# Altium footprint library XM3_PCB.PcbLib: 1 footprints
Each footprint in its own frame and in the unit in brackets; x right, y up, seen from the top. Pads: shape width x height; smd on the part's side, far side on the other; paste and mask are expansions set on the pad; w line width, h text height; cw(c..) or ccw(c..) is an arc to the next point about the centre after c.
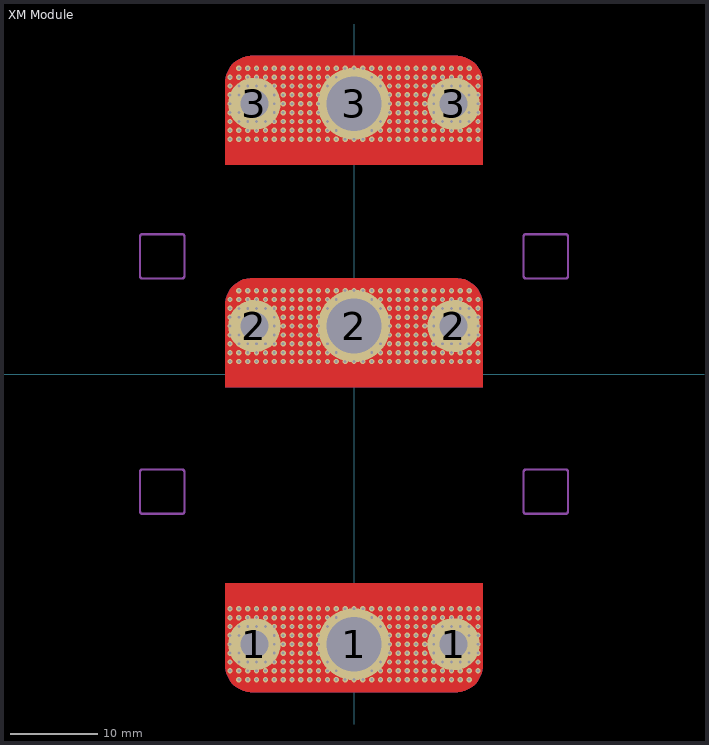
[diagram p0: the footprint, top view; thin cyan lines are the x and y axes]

## XM Module [mm]
pads (9):
  round 6 hole 3.2: 1(-11.43,-31) 1(11.43,-31) 2(-11.43,5.5) 2(11.43,5.5) 3(-11.43,31) 3(11.43,31)
  round 8.3 hole 6.3: 1(0,-31) 2(0,5.5) 3(0,31)
via 0,26.936 diameter 0.61 hole 0.33
via 1.016,26.936 diameter 0.61 hole 0.33
via 1.016,35.064 diameter 0.61 hole 0.33
via 2.032,26.936 diameter 0.61 hole 0.33
via 2.032,27.952 diameter 0.61 hole 0.33
via 2.032,34.048 diameter 0.61 hole 0.33
via 2.032,35.064 diameter 0.61 hole 0.33
via 3.048,26.936 diameter 0.61 hole 0.33
via 3.048,27.952 diameter 0.61 hole 0.33
via 3.048,28.968 diameter 0.61 hole 0.33
via 3.048,33.032 diameter 0.61 hole 0.33
via 3.048,34.048 diameter 0.61 hole 0.33
via 3.048,35.064 diameter 0.61 hole 0.33
via 4.064,26.936 diameter 0.61 hole 0.33
via 4.064,27.952 diameter 0.61 hole 0.33
via 4.064,28.968 diameter 0.61 hole 0.33
via 4.064,29.984 diameter 0.61 hole 0.33
via 4.064,31 diameter 0.61 hole 0.33
via 4.064,32.016 diameter 0.61 hole 0.33
via 4.064,33.032 diameter 0.61 hole 0.33
via 4.064,34.048 diameter 0.61 hole 0.33
via 4.064,35.064 diameter 0.61 hole 0.33
via 5.08,26.936 diameter 0.61 hole 0.33
via 5.08,27.952 diameter 0.61 hole 0.33
via 5.08,28.968 diameter 0.61 hole 0.33
via 5.08,29.984 diameter 0.61 hole 0.33
via 5.08,31 diameter 0.61 hole 0.33
via 5.08,32.016 diameter 0.61 hole 0.33
via 5.08,33.032 diameter 0.61 hole 0.33
via 5.08,34.048 diameter 0.61 hole 0.33
via 5.08,35.064 diameter 0.61 hole 0.33
via 6.096,26.936 diameter 0.61 hole 0.33
via 6.096,27.952 diameter 0.61 hole 0.33
via 6.096,28.968 diameter 0.61 hole 0.33
via 6.096,29.984 diameter 0.61 hole 0.33
via 6.096,31 diameter 0.61 hole 0.33
via 6.096,32.016 diameter 0.61 hole 0.33
via 6.096,33.032 diameter 0.61 hole 0.33
via 6.096,34.048 diameter 0.61 hole 0.33
via 6.096,35.064 diameter 0.61 hole 0.33
via 7.112,26.936 diameter 0.61 hole 0.33
via 7.112,27.952 diameter 0.61 hole 0.33
via 7.112,28.968 diameter 0.61 hole 0.33
via 7.112,29.984 diameter 0.61 hole 0.33
via 7.112,31 diameter 0.61 hole 0.33
via 7.112,32.016 diameter 0.61 hole 0.33
via 7.112,33.032 diameter 0.61 hole 0.33
via 7.112,34.048 diameter 0.61 hole 0.33
via 7.112,35.064 diameter 0.61 hole 0.33
via 8.128,26.936 diameter 0.61 hole 0.33
via 8.128,27.952 diameter 0.61 hole 0.33
via 8.128,28.968 diameter 0.61 hole 0.33
via 8.128,29.984 diameter 0.61 hole 0.33
via 8.128,31 diameter 0.61 hole 0.33
via 8.128,32.016 diameter 0.61 hole 0.33
via 8.128,33.032 diameter 0.61 hole 0.33
via 8.128,34.048 diameter 0.61 hole 0.33
via 8.128,35.064 diameter 0.61 hole 0.33
via 9.144,26.936 diameter 0.61 hole 0.33
via 9.144,27.952 diameter 0.61 hole 0.33
via 9.144,28.968 diameter 0.61 hole 0.33
via 9.144,29.984 diameter 0.61 hole 0.33
via 9.144,31 diameter 0.61 hole 0.33
via 9.144,32.016 diameter 0.61 hole 0.33
via 9.144,33.032 diameter 0.61 hole 0.33
via 9.144,34.048 diameter 0.61 hole 0.33
via 9.144,35.064 diameter 0.61 hole 0.33
via 10.16,26.936 diameter 0.61 hole 0.33
via 10.16,27.952 diameter 0.61 hole 0.33
via 10.16,28.968 diameter 0.61 hole 0.33
via 10.16,33.032 diameter 0.61 hole 0.33
via 10.16,34.048 diameter 0.61 hole 0.33
via 10.16,35.064 diameter 0.61 hole 0.33
via 11.176,26.936 diameter 0.61 hole 0.33
via 11.176,27.952 diameter 0.61 hole 0.33
via 11.176,28.968 diameter 0.61 hole 0.33
via 11.176,33.032 diameter 0.61 hole 0.33
via 11.176,34.048 diameter 0.61 hole 0.33
via 11.176,35.064 diameter 0.61 hole 0.33
via 12.192,26.936 diameter 0.61 hole 0.33
via 12.192,27.952 diameter 0.61 hole 0.33
via 12.192,28.968 diameter 0.61 hole 0.33
via 12.192,33.032 diameter 0.61 hole 0.33
via 12.192,34.048 diameter 0.61 hole 0.33
via 12.192,35.064 diameter 0.61 hole 0.33
via 13.208,26.936 diameter 0.61 hole 0.33
via 13.208,27.952 diameter 0.61 hole 0.33
via 13.208,28.968 diameter 0.61 hole 0.33
via 13.208,29.984 diameter 0.61 hole 0.33
via 13.208,32.016 diameter 0.61 hole 0.33
via 13.208,33.032 diameter 0.61 hole 0.33
via 13.208,34.048 diameter 0.61 hole 0.33
via 13.208,35.064 diameter 0.61 hole 0.33
via 14.224,26.936 diameter 0.61 hole 0.33
via 14.224,27.952 diameter 0.61 hole 0.33
via 14.224,28.968 diameter 0.61 hole 0.33
via 14.224,29.984 diameter 0.61 hole 0.33
via 14.224,31 diameter 0.61 hole 0.33
via 14.224,32.016 diameter 0.61 hole 0.33
via 14.224,33.032 diameter 0.61 hole 0.33
via 14.224,34.048 diameter 0.61 hole 0.33
via 0,35.064 diameter 0.61 hole 0.33
via -1.016,26.936 diameter 0.61 hole 0.33
via -1.016,35.064 diameter 0.61 hole 0.33
via -2.032,26.936 diameter 0.61 hole 0.33
via -2.032,27.952 diameter 0.61 hole 0.33
via -2.032,34.048 diameter 0.61 hole 0.33
via -2.032,35.064 diameter 0.61 hole 0.33
via -3.048,26.936 diameter 0.61 hole 0.33
via -3.048,27.952 diameter 0.61 hole 0.33
via -3.048,28.968 diameter 0.61 hole 0.33
via -3.048,33.032 diameter 0.61 hole 0.33
via -3.048,34.048 diameter 0.61 hole 0.33
via -3.048,35.064 diameter 0.61 hole 0.33
via -4.064,26.936 diameter 0.61 hole 0.33
via -4.064,27.952 diameter 0.61 hole 0.33
via -4.064,28.968 diameter 0.61 hole 0.33
via -4.064,29.984 diameter 0.61 hole 0.33
via -4.064,31 diameter 0.61 hole 0.33
via -4.064,32.016 diameter 0.61 hole 0.33
via -4.064,33.032 diameter 0.61 hole 0.33
via -4.064,34.048 diameter 0.61 hole 0.33
via -4.064,35.064 diameter 0.61 hole 0.33
via -5.08,26.936 diameter 0.61 hole 0.33
via -5.08,27.952 diameter 0.61 hole 0.33
via -5.08,28.968 diameter 0.61 hole 0.33
via -5.08,29.984 diameter 0.61 hole 0.33
via -5.08,31 diameter 0.61 hole 0.33
via -5.08,32.016 diameter 0.61 hole 0.33
via -5.08,33.032 diameter 0.61 hole 0.33
via -5.08,34.048 diameter 0.61 hole 0.33
via -5.08,35.064 diameter 0.61 hole 0.33
via -6.096,26.936 diameter 0.61 hole 0.33
via -6.096,27.952 diameter 0.61 hole 0.33
via -6.096,28.968 diameter 0.61 hole 0.33
via -6.096,29.984 diameter 0.61 hole 0.33
via -6.096,31 diameter 0.61 hole 0.33
via -6.096,32.016 diameter 0.61 hole 0.33
via -6.096,33.032 diameter 0.61 hole 0.33
via -6.096,34.048 diameter 0.61 hole 0.33
via -6.096,35.064 diameter 0.61 hole 0.33
via -7.112,26.936 diameter 0.61 hole 0.33
via -7.112,27.952 diameter 0.61 hole 0.33
via -7.112,28.968 diameter 0.61 hole 0.33
via -7.112,29.984 diameter 0.61 hole 0.33
via -7.112,31 diameter 0.61 hole 0.33
via -7.112,32.016 diameter 0.61 hole 0.33
via -7.112,33.032 diameter 0.61 hole 0.33
via -7.112,34.048 diameter 0.61 hole 0.33
via -7.112,35.064 diameter 0.61 hole 0.33
via -8.128,26.936 diameter 0.61 hole 0.33
via -8.128,27.952 diameter 0.61 hole 0.33
via -8.128,28.968 diameter 0.61 hole 0.33
via -8.128,29.984 diameter 0.61 hole 0.33
via -8.128,31 diameter 0.61 hole 0.33
via -8.128,32.016 diameter 0.61 hole 0.33
via -8.128,33.032 diameter 0.61 hole 0.33
via -8.128,34.048 diameter 0.61 hole 0.33
via -8.128,35.064 diameter 0.61 hole 0.33
via -9.144,26.936 diameter 0.61 hole 0.33
via -9.144,27.952 diameter 0.61 hole 0.33
via -9.144,28.968 diameter 0.61 hole 0.33
via -9.144,29.984 diameter 0.61 hole 0.33
via -9.144,31 diameter 0.61 hole 0.33
via -9.144,32.016 diameter 0.61 hole 0.33
via -9.144,33.032 diameter 0.61 hole 0.33
via -9.144,34.048 diameter 0.61 hole 0.33
via -9.144,35.064 diameter 0.61 hole 0.33
via -10.16,26.936 diameter 0.61 hole 0.33
via -10.16,27.952 diameter 0.61 hole 0.33
via -10.16,28.968 diameter 0.61 hole 0.33
via -10.16,33.032 diameter 0.61 hole 0.33
via -10.16,34.048 diameter 0.61 hole 0.33
via -10.16,35.064 diameter 0.61 hole 0.33
via -11.176,26.936 diameter 0.61 hole 0.33
via -11.176,27.952 diameter 0.61 hole 0.33
via -11.176,28.968 diameter 0.61 hole 0.33
via -11.176,33.032 diameter 0.61 hole 0.33
via -11.176,34.048 diameter 0.61 hole 0.33
via -11.176,35.064 diameter 0.61 hole 0.33
via -12.192,26.936 diameter 0.61 hole 0.33
via -12.192,27.952 diameter 0.61 hole 0.33
via -12.192,28.968 diameter 0.61 hole 0.33
via -12.192,33.032 diameter 0.61 hole 0.33
via -12.192,34.048 diameter 0.61 hole 0.33
via -12.192,35.064 diameter 0.61 hole 0.33
via -13.208,26.936 diameter 0.61 hole 0.33
via -13.208,27.952 diameter 0.61 hole 0.33
via -13.208,28.968 diameter 0.61 hole 0.33
via -13.208,29.984 diameter 0.61 hole 0.33
via -13.208,32.016 diameter 0.61 hole 0.33
via -13.208,33.032 diameter 0.61 hole 0.33
via -13.208,34.048 diameter 0.61 hole 0.33
via -13.208,35.064 diameter 0.61 hole 0.33
via -14.224,26.936 diameter 0.61 hole 0.33
via -14.224,27.952 diameter 0.61 hole 0.33
via -14.224,28.968 diameter 0.61 hole 0.33
via -14.224,29.984 diameter 0.61 hole 0.33
via -14.224,31 diameter 0.61 hole 0.33
via -14.224,32.016 diameter 0.61 hole 0.33
via -14.224,33.032 diameter 0.61 hole 0.33
via -14.224,34.048 diameter 0.61 hole 0.33
via 0,1.436 diameter 0.61 hole 0.33
via 1.016,1.436 diameter 0.61 hole 0.33
via 1.016,9.564 diameter 0.61 hole 0.33
via 2.032,1.436 diameter 0.61 hole 0.33
via 2.032,2.452 diameter 0.61 hole 0.33
via 2.032,8.548 diameter 0.61 hole 0.33
via 2.032,9.564 diameter 0.61 hole 0.33
via 3.048,1.436 diameter 0.61 hole 0.33
via 3.048,2.452 diameter 0.61 hole 0.33
via 3.048,3.468 diameter 0.61 hole 0.33
via 3.048,7.532 diameter 0.61 hole 0.33
via 3.048,8.548 diameter 0.61 hole 0.33
via 3.048,9.564 diameter 0.61 hole 0.33
via 4.064,1.436 diameter 0.61 hole 0.33
via 4.064,2.452 diameter 0.61 hole 0.33
via 4.064,3.468 diameter 0.61 hole 0.33
via 4.064,4.484 diameter 0.61 hole 0.33
via 4.064,5.5 diameter 0.61 hole 0.33
via 4.064,6.516 diameter 0.61 hole 0.33
via 4.064,7.532 diameter 0.61 hole 0.33
via 4.064,8.548 diameter 0.61 hole 0.33
via 4.064,9.564 diameter 0.61 hole 0.33
via 5.08,1.436 diameter 0.61 hole 0.33
via 5.08,2.452 diameter 0.61 hole 0.33
via 5.08,3.468 diameter 0.61 hole 0.33
via 5.08,4.484 diameter 0.61 hole 0.33
via 5.08,5.5 diameter 0.61 hole 0.33
via 5.08,6.516 diameter 0.61 hole 0.33
via 5.08,7.532 diameter 0.61 hole 0.33
via 5.08,8.548 diameter 0.61 hole 0.33
via 5.08,9.564 diameter 0.61 hole 0.33
via 6.096,1.436 diameter 0.61 hole 0.33
via 6.096,2.452 diameter 0.61 hole 0.33
via 6.096,3.468 diameter 0.61 hole 0.33
via 6.096,4.484 diameter 0.61 hole 0.33
via 6.096,5.5 diameter 0.61 hole 0.33
via 6.096,6.516 diameter 0.61 hole 0.33
via 6.096,7.532 diameter 0.61 hole 0.33
via 6.096,8.548 diameter 0.61 hole 0.33
via 6.096,9.564 diameter 0.61 hole 0.33
via 7.112,1.436 diameter 0.61 hole 0.33
via 7.112,2.452 diameter 0.61 hole 0.33
via 7.112,3.468 diameter 0.61 hole 0.33
via 7.112,4.484 diameter 0.61 hole 0.33
via 7.112,5.5 diameter 0.61 hole 0.33
via 7.112,6.516 diameter 0.61 hole 0.33
via 7.112,7.532 diameter 0.61 hole 0.33
via 7.112,8.548 diameter 0.61 hole 0.33
via 7.112,9.564 diameter 0.61 hole 0.33
via 8.128,1.436 diameter 0.61 hole 0.33
via 8.128,2.452 diameter 0.61 hole 0.33
via 8.128,3.468 diameter 0.61 hole 0.33
via 8.128,4.484 diameter 0.61 hole 0.33
via 8.128,5.5 diameter 0.61 hole 0.33
via 8.128,6.516 diameter 0.61 hole 0.33
via 8.128,7.532 diameter 0.61 hole 0.33
via 8.128,8.548 diameter 0.61 hole 0.33
via 8.128,9.564 diameter 0.61 hole 0.33
via 9.144,1.436 diameter 0.61 hole 0.33
via 9.144,2.452 diameter 0.61 hole 0.33
via 9.144,3.468 diameter 0.61 hole 0.33
via 9.144,4.484 diameter 0.61 hole 0.33
via 9.144,5.5 diameter 0.61 hole 0.33
via 9.144,6.516 diameter 0.61 hole 0.33
via 9.144,7.532 diameter 0.61 hole 0.33
via 9.144,8.548 diameter 0.61 hole 0.33
via 9.144,9.564 diameter 0.61 hole 0.33
via 10.16,1.436 diameter 0.61 hole 0.33
via 10.16,2.452 diameter 0.61 hole 0.33
via 10.16,3.468 diameter 0.61 hole 0.33
via 10.16,7.532 diameter 0.61 hole 0.33
via 10.16,8.548 diameter 0.61 hole 0.33
via 10.16,9.564 diameter 0.61 hole 0.33
via 11.176,1.436 diameter 0.61 hole 0.33
via 11.176,2.452 diameter 0.61 hole 0.33
via 11.176,3.468 diameter 0.61 hole 0.33
via 11.176,7.532 diameter 0.61 hole 0.33
via 11.176,8.548 diameter 0.61 hole 0.33
via 11.176,9.564 diameter 0.61 hole 0.33
via 12.192,1.436 diameter 0.61 hole 0.33
via 12.192,2.452 diameter 0.61 hole 0.33
via 12.192,3.468 diameter 0.61 hole 0.33
via 12.192,7.532 diameter 0.61 hole 0.33
via 12.192,8.548 diameter 0.61 hole 0.33
via 12.192,9.564 diameter 0.61 hole 0.33
via 13.208,1.436 diameter 0.61 hole 0.33
via 13.208,2.452 diameter 0.61 hole 0.33
via 13.208,3.468 diameter 0.61 hole 0.33
via 13.208,4.484 diameter 0.61 hole 0.33
via 13.208,6.516 diameter 0.61 hole 0.33
via 13.208,7.532 diameter 0.61 hole 0.33
via 13.208,8.548 diameter 0.61 hole 0.33
via 13.208,9.564 diameter 0.61 hole 0.33
via 14.224,1.436 diameter 0.61 hole 0.33
via 14.224,2.452 diameter 0.61 hole 0.33
via 14.224,3.468 diameter 0.61 hole 0.33
via 14.224,4.484 diameter 0.61 hole 0.33
via 14.224,5.5 diameter 0.61 hole 0.33
via 14.224,6.516 diameter 0.61 hole 0.33
via 14.224,7.532 diameter 0.61 hole 0.33
via 14.224,8.548 diameter 0.61 hole 0.33
via 0,9.564 diameter 0.61 hole 0.33
via -1.016,1.436 diameter 0.61 hole 0.33
via -1.016,9.564 diameter 0.61 hole 0.33
via -2.032,1.436 diameter 0.61 hole 0.33
via -2.032,2.452 diameter 0.61 hole 0.33
via -2.032,8.548 diameter 0.61 hole 0.33
via -2.032,9.564 diameter 0.61 hole 0.33
via -3.048,1.436 diameter 0.61 hole 0.33
via -3.048,2.452 diameter 0.61 hole 0.33
via -3.048,3.468 diameter 0.61 hole 0.33
via -3.048,7.532 diameter 0.61 hole 0.33
via -3.048,8.548 diameter 0.61 hole 0.33
via -3.048,9.564 diameter 0.61 hole 0.33
via -4.064,1.436 diameter 0.61 hole 0.33
via -4.064,2.452 diameter 0.61 hole 0.33
via -4.064,3.468 diameter 0.61 hole 0.33
via -4.064,4.484 diameter 0.61 hole 0.33
via -4.064,5.5 diameter 0.61 hole 0.33
via -4.064,6.516 diameter 0.61 hole 0.33
via -4.064,7.532 diameter 0.61 hole 0.33
via -4.064,8.548 diameter 0.61 hole 0.33
via -4.064,9.564 diameter 0.61 hole 0.33
via -5.08,1.436 diameter 0.61 hole 0.33
via -5.08,2.452 diameter 0.61 hole 0.33
via -5.08,3.468 diameter 0.61 hole 0.33
via -5.08,4.484 diameter 0.61 hole 0.33
via -5.08,5.5 diameter 0.61 hole 0.33
via -5.08,6.516 diameter 0.61 hole 0.33
via -5.08,7.532 diameter 0.61 hole 0.33
via -5.08,8.548 diameter 0.61 hole 0.33
via -5.08,9.564 diameter 0.61 hole 0.33
via -6.096,1.436 diameter 0.61 hole 0.33
via -6.096,2.452 diameter 0.61 hole 0.33
via -6.096,3.468 diameter 0.61 hole 0.33
via -6.096,4.484 diameter 0.61 hole 0.33
via -6.096,5.5 diameter 0.61 hole 0.33
via -6.096,6.516 diameter 0.61 hole 0.33
via -6.096,7.532 diameter 0.61 hole 0.33
via -6.096,8.548 diameter 0.61 hole 0.33
via -6.096,9.564 diameter 0.61 hole 0.33
via -7.112,1.436 diameter 0.61 hole 0.33
via -7.112,2.452 diameter 0.61 hole 0.33
via -7.112,3.468 diameter 0.61 hole 0.33
via -7.112,4.484 diameter 0.61 hole 0.33
via -7.112,5.5 diameter 0.61 hole 0.33
via -7.112,6.516 diameter 0.61 hole 0.33
via -7.112,7.532 diameter 0.61 hole 0.33
via -7.112,8.548 diameter 0.61 hole 0.33
via -7.112,9.564 diameter 0.61 hole 0.33
via -8.128,1.436 diameter 0.61 hole 0.33
via -8.128,2.452 diameter 0.61 hole 0.33
via -8.128,3.468 diameter 0.61 hole 0.33
via -8.128,4.484 diameter 0.61 hole 0.33
via -8.128,5.5 diameter 0.61 hole 0.33
via -8.128,6.516 diameter 0.61 hole 0.33
via -8.128,7.532 diameter 0.61 hole 0.33
via -8.128,8.548 diameter 0.61 hole 0.33
via -8.128,9.564 diameter 0.61 hole 0.33
via -9.144,1.436 diameter 0.61 hole 0.33
via -9.144,2.452 diameter 0.61 hole 0.33
via -9.144,3.468 diameter 0.61 hole 0.33
via -9.144,4.484 diameter 0.61 hole 0.33
via -9.144,5.5 diameter 0.61 hole 0.33
via -9.144,6.516 diameter 0.61 hole 0.33
via -9.144,7.532 diameter 0.61 hole 0.33
via -9.144,8.548 diameter 0.61 hole 0.33
via -9.144,9.564 diameter 0.61 hole 0.33
via -10.16,1.436 diameter 0.61 hole 0.33
via -10.16,2.452 diameter 0.61 hole 0.33
via -10.16,3.468 diameter 0.61 hole 0.33
via -10.16,7.532 diameter 0.61 hole 0.33
via -10.16,8.548 diameter 0.61 hole 0.33
via -10.16,9.564 diameter 0.61 hole 0.33
via -11.176,1.436 diameter 0.61 hole 0.33
via -11.176,2.452 diameter 0.61 hole 0.33
via -11.176,3.468 diameter 0.61 hole 0.33
via -11.176,7.532 diameter 0.61 hole 0.33
via -11.176,8.548 diameter 0.61 hole 0.33
via -11.176,9.564 diameter 0.61 hole 0.33
via -12.192,1.436 diameter 0.61 hole 0.33
via -12.192,2.452 diameter 0.61 hole 0.33
via -12.192,3.468 diameter 0.61 hole 0.33
via -12.192,7.532 diameter 0.61 hole 0.33
via -12.192,8.548 diameter 0.61 hole 0.33
via -12.192,9.564 diameter 0.61 hole 0.33
via -13.208,1.436 diameter 0.61 hole 0.33
via -13.208,2.452 diameter 0.61 hole 0.33
via -13.208,3.468 diameter 0.61 hole 0.33
via -13.208,4.484 diameter 0.61 hole 0.33
via -13.208,6.516 diameter 0.61 hole 0.33
via -13.208,7.532 diameter 0.61 hole 0.33
via -13.208,8.548 diameter 0.61 hole 0.33
via -13.208,9.564 diameter 0.61 hole 0.33
via -14.224,1.436 diameter 0.61 hole 0.33
via -14.224,2.452 diameter 0.61 hole 0.33
via -14.224,3.468 diameter 0.61 hole 0.33
via -14.224,4.484 diameter 0.61 hole 0.33
via -14.224,5.5 diameter 0.61 hole 0.33
via -14.224,6.516 diameter 0.61 hole 0.33
via -14.224,7.532 diameter 0.61 hole 0.33
via -14.224,8.548 diameter 0.61 hole 0.33
via 0,-26.936 diameter 0.61 hole 0.33
via 1.016,-26.936 diameter 0.61 hole 0.33
via 1.016,-35.064 diameter 0.61 hole 0.33
via 2.032,-26.936 diameter 0.61 hole 0.33
via 2.032,-27.952 diameter 0.61 hole 0.33
via 2.032,-34.048 diameter 0.61 hole 0.33
via 2.032,-35.064 diameter 0.61 hole 0.33
via 3.048,-26.936 diameter 0.61 hole 0.33
via 3.048,-27.952 diameter 0.61 hole 0.33
via 3.048,-28.968 diameter 0.61 hole 0.33
via 3.048,-33.032 diameter 0.61 hole 0.33
via 3.048,-34.048 diameter 0.61 hole 0.33
via 3.048,-35.064 diameter 0.61 hole 0.33
via 4.064,-26.936 diameter 0.61 hole 0.33
via 4.064,-27.952 diameter 0.61 hole 0.33
via 4.064,-28.968 diameter 0.61 hole 0.33
via 4.064,-29.984 diameter 0.61 hole 0.33
via 4.064,-31 diameter 0.61 hole 0.33
via 4.064,-32.016 diameter 0.61 hole 0.33
via 4.064,-33.032 diameter 0.61 hole 0.33
via 4.064,-34.048 diameter 0.61 hole 0.33
via 4.064,-35.064 diameter 0.61 hole 0.33
via 5.08,-26.936 diameter 0.61 hole 0.33
via 5.08,-27.952 diameter 0.61 hole 0.33
via 5.08,-28.968 diameter 0.61 hole 0.33
via 5.08,-29.984 diameter 0.61 hole 0.33
via 5.08,-31 diameter 0.61 hole 0.33
via 5.08,-32.016 diameter 0.61 hole 0.33
via 5.08,-33.032 diameter 0.61 hole 0.33
via 5.08,-34.048 diameter 0.61 hole 0.33
via 5.08,-35.064 diameter 0.61 hole 0.33
via 6.096,-26.936 diameter 0.61 hole 0.33
via 6.096,-27.952 diameter 0.61 hole 0.33
via 6.096,-28.968 diameter 0.61 hole 0.33
via 6.096,-29.984 diameter 0.61 hole 0.33
via 6.096,-31 diameter 0.61 hole 0.33
via 6.096,-32.016 diameter 0.61 hole 0.33
via 6.096,-33.032 diameter 0.61 hole 0.33
via 6.096,-34.048 diameter 0.61 hole 0.33
via 6.096,-35.064 diameter 0.61 hole 0.33
via 7.112,-26.936 diameter 0.61 hole 0.33
via 7.112,-27.952 diameter 0.61 hole 0.33
via 7.112,-28.968 diameter 0.61 hole 0.33
via 7.112,-29.984 diameter 0.61 hole 0.33
via 7.112,-31 diameter 0.61 hole 0.33
via 7.112,-32.016 diameter 0.61 hole 0.33
via 7.112,-33.032 diameter 0.61 hole 0.33
via 7.112,-34.048 diameter 0.61 hole 0.33
via 7.112,-35.064 diameter 0.61 hole 0.33
via 8.128,-26.936 diameter 0.61 hole 0.33
via 8.128,-27.952 diameter 0.61 hole 0.33
via 8.128,-28.968 diameter 0.61 hole 0.33
via 8.128,-29.984 diameter 0.61 hole 0.33
via 8.128,-31 diameter 0.61 hole 0.33
via 8.128,-32.016 diameter 0.61 hole 0.33
via 8.128,-33.032 diameter 0.61 hole 0.33
via 8.128,-34.048 diameter 0.61 hole 0.33
via 8.128,-35.064 diameter 0.61 hole 0.33
via 9.144,-26.936 diameter 0.61 hole 0.33
via 9.144,-27.952 diameter 0.61 hole 0.33
via 9.144,-28.968 diameter 0.61 hole 0.33
via 9.144,-29.984 diameter 0.61 hole 0.33
via 9.144,-31 diameter 0.61 hole 0.33
via 9.144,-32.016 diameter 0.61 hole 0.33
via 9.144,-33.032 diameter 0.61 hole 0.33
via 9.144,-34.048 diameter 0.61 hole 0.33
via 9.144,-35.064 diameter 0.61 hole 0.33
via 10.16,-26.936 diameter 0.61 hole 0.33
via 10.16,-27.952 diameter 0.61 hole 0.33
via 10.16,-28.968 diameter 0.61 hole 0.33
via 10.16,-33.032 diameter 0.61 hole 0.33
via 10.16,-34.048 diameter 0.61 hole 0.33
via 10.16,-35.064 diameter 0.61 hole 0.33
via 11.176,-26.936 diameter 0.61 hole 0.33
via 11.176,-27.952 diameter 0.61 hole 0.33
via 11.176,-28.968 diameter 0.61 hole 0.33
via 11.176,-33.032 diameter 0.61 hole 0.33
via 11.176,-34.048 diameter 0.61 hole 0.33
via 11.176,-35.064 diameter 0.61 hole 0.33
via 12.192,-26.936 diameter 0.61 hole 0.33
via 12.192,-27.952 diameter 0.61 hole 0.33
via 12.192,-28.968 diameter 0.61 hole 0.33
via 12.192,-33.032 diameter 0.61 hole 0.33
via 12.192,-34.048 diameter 0.61 hole 0.33
via 12.192,-35.064 diameter 0.61 hole 0.33
via 13.208,-26.936 diameter 0.61 hole 0.33
via 13.208,-27.952 diameter 0.61 hole 0.33
via 13.208,-28.968 diameter 0.61 hole 0.33
via 13.208,-29.984 diameter 0.61 hole 0.33
via 13.208,-32.016 diameter 0.61 hole 0.33
via 13.208,-33.032 diameter 0.61 hole 0.33
via 13.208,-34.048 diameter 0.61 hole 0.33
via 13.208,-35.064 diameter 0.61 hole 0.33
via 14.224,-26.936 diameter 0.61 hole 0.33
via 14.224,-27.952 diameter 0.61 hole 0.33
via 14.224,-28.968 diameter 0.61 hole 0.33
via 14.224,-29.984 diameter 0.61 hole 0.33
via 14.224,-31 diameter 0.61 hole 0.33
via 14.224,-32.016 diameter 0.61 hole 0.33
via 14.224,-33.032 diameter 0.61 hole 0.33
via 14.224,-34.048 diameter 0.61 hole 0.33
via 0,-35.064 diameter 0.61 hole 0.33
via -1.016,-26.936 diameter 0.61 hole 0.33
via -1.016,-35.064 diameter 0.61 hole 0.33
via -2.032,-26.936 diameter 0.61 hole 0.33
via -2.032,-27.952 diameter 0.61 hole 0.33
via -2.032,-34.048 diameter 0.61 hole 0.33
via -2.032,-35.064 diameter 0.61 hole 0.33
via -3.048,-26.936 diameter 0.61 hole 0.33
via -3.048,-27.952 diameter 0.61 hole 0.33
via -3.048,-28.968 diameter 0.61 hole 0.33
via -3.048,-33.032 diameter 0.61 hole 0.33
via -3.048,-34.048 diameter 0.61 hole 0.33
via -3.048,-35.064 diameter 0.61 hole 0.33
via -4.064,-26.936 diameter 0.61 hole 0.33
via -4.064,-27.952 diameter 0.61 hole 0.33
via -4.064,-28.968 diameter 0.61 hole 0.33
via -4.064,-29.984 diameter 0.61 hole 0.33
via -4.064,-31 diameter 0.61 hole 0.33
via -4.064,-32.016 diameter 0.61 hole 0.33
via -4.064,-33.032 diameter 0.61 hole 0.33
via -4.064,-34.048 diameter 0.61 hole 0.33
via -4.064,-35.064 diameter 0.61 hole 0.33
via -5.08,-26.936 diameter 0.61 hole 0.33
via -5.08,-27.952 diameter 0.61 hole 0.33
via -5.08,-28.968 diameter 0.61 hole 0.33
via -5.08,-29.984 diameter 0.61 hole 0.33
via -5.08,-31 diameter 0.61 hole 0.33
via -5.08,-32.016 diameter 0.61 hole 0.33
via -5.08,-33.032 diameter 0.61 hole 0.33
via -5.08,-34.048 diameter 0.61 hole 0.33
via -5.08,-35.064 diameter 0.61 hole 0.33
via -6.096,-26.936 diameter 0.61 hole 0.33
via -6.096,-27.952 diameter 0.61 hole 0.33
via -6.096,-28.968 diameter 0.61 hole 0.33
via -6.096,-29.984 diameter 0.61 hole 0.33
via -6.096,-31 diameter 0.61 hole 0.33
via -6.096,-32.016 diameter 0.61 hole 0.33
via -6.096,-33.032 diameter 0.61 hole 0.33
via -6.096,-34.048 diameter 0.61 hole 0.33
via -6.096,-35.064 diameter 0.61 hole 0.33
via -7.112,-26.936 diameter 0.61 hole 0.33
via -7.112,-27.952 diameter 0.61 hole 0.33
via -7.112,-28.968 diameter 0.61 hole 0.33
via -7.112,-29.984 diameter 0.61 hole 0.33
via -7.112,-31 diameter 0.61 hole 0.33
via -7.112,-32.016 diameter 0.61 hole 0.33
via -7.112,-33.032 diameter 0.61 hole 0.33
via -7.112,-34.048 diameter 0.61 hole 0.33
via -7.112,-35.064 diameter 0.61 hole 0.33
via -8.128,-26.936 diameter 0.61 hole 0.33
via -8.128,-27.952 diameter 0.61 hole 0.33
via -8.128,-28.968 diameter 0.61 hole 0.33
via -8.128,-29.984 diameter 0.61 hole 0.33
via -8.128,-31 diameter 0.61 hole 0.33
via -8.128,-32.016 diameter 0.61 hole 0.33
via -8.128,-33.032 diameter 0.61 hole 0.33
via -8.128,-34.048 diameter 0.61 hole 0.33
via -8.128,-35.064 diameter 0.61 hole 0.33
via -9.144,-26.936 diameter 0.61 hole 0.33
via -9.144,-27.952 diameter 0.61 hole 0.33
via -9.144,-28.968 diameter 0.61 hole 0.33
via -9.144,-29.984 diameter 0.61 hole 0.33
via -9.144,-31 diameter 0.61 hole 0.33
via -9.144,-32.016 diameter 0.61 hole 0.33
via -9.144,-33.032 diameter 0.61 hole 0.33
via -9.144,-34.048 diameter 0.61 hole 0.33
via -9.144,-35.064 diameter 0.61 hole 0.33
via -10.16,-26.936 diameter 0.61 hole 0.33
via -10.16,-27.952 diameter 0.61 hole 0.33
via -10.16,-28.968 diameter 0.61 hole 0.33
via -10.16,-33.032 diameter 0.61 hole 0.33
via -10.16,-34.048 diameter 0.61 hole 0.33
via -10.16,-35.064 diameter 0.61 hole 0.33
via -11.176,-26.936 diameter 0.61 hole 0.33
via -11.176,-27.952 diameter 0.61 hole 0.33
via -11.176,-28.968 diameter 0.61 hole 0.33
via -11.176,-33.032 diameter 0.61 hole 0.33
via -11.176,-34.048 diameter 0.61 hole 0.33
via -11.176,-35.064 diameter 0.61 hole 0.33
via -12.192,-26.936 diameter 0.61 hole 0.33
via -12.192,-27.952 diameter 0.61 hole 0.33
via -12.192,-28.968 diameter 0.61 hole 0.33
via -12.192,-33.032 diameter 0.61 hole 0.33
via -12.192,-34.048 diameter 0.61 hole 0.33
via -12.192,-35.064 diameter 0.61 hole 0.33
via -13.208,-26.936 diameter 0.61 hole 0.33
via -13.208,-27.952 diameter 0.61 hole 0.33
via -13.208,-28.968 diameter 0.61 hole 0.33
via -13.208,-29.984 diameter 0.61 hole 0.33
via -13.208,-32.016 diameter 0.61 hole 0.33
via -13.208,-33.032 diameter 0.61 hole 0.33
via -13.208,-34.048 diameter 0.61 hole 0.33
via -13.208,-35.064 diameter 0.61 hole 0.33
via -14.224,-26.936 diameter 0.61 hole 0.33
via -14.224,-27.952 diameter 0.61 hole 0.33
via -14.224,-28.968 diameter 0.61 hole 0.33
via -14.224,-29.984 diameter 0.61 hole 0.33
via -14.224,-31 diameter 0.61 hole 0.33
via -14.224,-32.016 diameter 0.61 hole 0.33
via -14.224,-33.032 diameter 0.61 hole 0.33
via -14.224,-34.048 diameter 0.61 hole 0.33
Top Layer:
  region: -14.75,-24 14.75,-24 14.75,-33.452 14.75,-33.652 14.698,-34.048 14.594,-34.434 14.442,-34.803 14.242,-35.149 13.999,-35.466 13.716,-35.749 13.399,-35.992 13.053,-36.192 12.684,-36.344 12.298,-36.448 11.902,-36.5 11.702,-36.5 -11.702,-36.5 -11.902,-36.5 -12.298,-36.448 -12.684,-36.344 -13.053,-36.192 -13.399,-35.992 -13.716,-35.749 -13.999,-35.466 -14.242,-35.149 -14.442,-34.803 -14.594,-34.434 -14.698,-34.048 -14.75,-33.652 -14.75,-33.452 -14.75,-25
  region: -14.75,-24 14.75,-24 14.75,-33.452 14.75,-33.652 14.698,-34.048 14.594,-34.434 14.442,-34.803 14.242,-35.149 13.999,-35.466 13.716,-35.749 13.399,-35.992 13.053,-36.192 12.684,-36.344 12.298,-36.448 11.902,-36.5 11.702,-36.5 -11.702,-36.5 -11.902,-36.5 -12.298,-36.448 -12.684,-36.344 -13.053,-36.192 -13.399,-35.992 -13.716,-35.749 -13.999,-35.466 -14.242,-35.149 -14.442,-34.803 -14.594,-34.434 -14.698,-34.048 -14.75,-33.652 -14.75,-33.452 -14.75,-25
  region: -14.75,24 14.768,24 14.768,33.452 14.768,33.652 14.716,34.048 14.612,34.434 14.459,34.803 14.259,35.149 14.016,35.466 13.734,35.749 13.417,35.992 13.071,36.192 12.702,36.344 12.316,36.448 11.919,36.5 11.72,36.5 -11.702,36.5 -11.902,36.5 -12.298,36.448 -12.684,36.344 -13.053,36.192 -13.399,35.992 -13.716,35.749 -13.999,35.466 -14.242,35.149 -14.442,34.803 -14.594,34.434 -14.698,34.048 -14.75,33.652 -14.75,33.452 -14.75,28.75
  region: -14.75,-1.5 14.75,-1.5 14.75,7.952 14.75,8.152 14.698,8.548 14.594,8.934 14.442,9.303 14.242,9.649 13.999,9.966 13.716,10.249 13.399,10.492 13.053,10.692 12.684,10.844 12.298,10.948 11.902,11 11.702,11 -11.702,11 -11.902,11 -12.298,10.948 -12.684,10.844 -13.053,10.692 -13.399,10.492 -13.716,10.249 -13.999,9.966 -14.242,9.649 -14.442,9.303 -14.594,8.934 -14.698,8.548 -14.75,8.152 -14.75,7.952 -14.75,2.236
Bottom Layer:
  region: -14.75,24 14.768,24 14.768,33.452 14.768,33.652 14.716,34.048 14.612,34.434 14.459,34.803 14.259,35.149 14.016,35.466 13.734,35.749 13.417,35.992 13.071,36.192 12.702,36.344 12.316,36.448 11.919,36.5 11.72,36.5 -11.702,36.5 -11.902,36.5 -12.298,36.448 -12.684,36.344 -13.053,36.192 -13.399,35.992 -13.716,35.749 -13.999,35.466 -14.242,35.149 -14.442,34.803 -14.594,34.434 -14.698,34.048 -14.75,33.652 -14.75,33.452 -14.75,28.75
  region: -14.75,-1.5 14.75,-1.5 14.75,7.952 14.75,8.152 14.698,8.548 14.594,8.934 14.442,9.303 14.242,9.649 13.999,9.966 13.716,10.249 13.399,10.492 13.053,10.692 12.684,10.844 12.298,10.948 11.902,11 11.702,11 -11.702,11 -11.902,11 -12.298,10.948 -12.684,10.844 -13.053,10.692 -13.399,10.492 -13.716,10.249 -13.999,9.966 -14.242,9.649 -14.442,9.303 -14.594,8.934 -14.698,8.548 -14.75,8.152 -14.75,7.952 -14.75,2.236
  region: -14.75,-24 14.75,-24 14.75,-33.452 14.75,-33.652 14.698,-34.048 14.594,-34.434 14.442,-34.803 14.242,-35.149 13.999,-35.466 13.716,-35.749 13.399,-35.992 13.053,-36.192 12.684,-36.344 12.298,-36.448 11.902,-36.5 11.702,-36.5 -11.702,-36.5 -11.902,-36.5 -12.298,-36.448 -12.684,-36.344 -13.053,-36.192 -13.399,-35.992 -13.716,-35.749 -13.999,-35.466 -14.242,-35.149 -14.442,-34.803 -14.594,-34.434 -14.698,-34.048 -14.75,-33.652 -14.75,-33.452 -14.75,-25
Top Solder:
  region: -14.75,-24 14.75,-24 14.75,-33.452 14.75,-33.652 14.698,-34.048 14.594,-34.434 14.442,-34.803 14.242,-35.149 13.999,-35.466 13.716,-35.749 13.399,-35.992 13.053,-36.192 12.684,-36.344 12.298,-36.448 11.902,-36.5 11.702,-36.5 -11.702,-36.5 -11.902,-36.5 -12.298,-36.448 -12.684,-36.344 -13.053,-36.192 -13.399,-35.992 -13.716,-35.749 -13.999,-35.466 -14.242,-35.149 -14.442,-34.803 -14.594,-34.434 -14.698,-34.048 -14.75,-33.652 -14.75,-33.452 -14.75,-25
  region: -14.75,24 14.768,24 14.768,33.452 14.768,33.652 14.716,34.048 14.612,34.434 14.459,34.803 14.259,35.149 14.016,35.466 13.734,35.749 13.417,35.992 13.071,36.192 12.702,36.344 12.316,36.448 11.919,36.5 11.72,36.5 -11.702,36.5 -11.902,36.5 -12.298,36.448 -12.684,36.344 -13.053,36.192 -13.399,35.992 -13.716,35.749 -13.999,35.466 -14.242,35.149 -14.442,34.803 -14.594,34.434 -14.698,34.048 -14.75,33.652 -14.75,33.452 -14.75,28.75
  region: -14.75,-1.5 14.75,-1.5 14.75,7.952 14.75,8.152 14.698,8.548 14.594,8.934 14.442,9.303 14.242,9.649 13.999,9.966 13.716,10.249 13.399,10.492 13.053,10.692 12.684,10.844 12.298,10.948 11.902,11 11.702,11 -11.702,11 -11.902,11 -12.298,10.948 -12.684,10.844 -13.053,10.692 -13.399,10.492 -13.716,10.249 -13.999,9.966 -14.242,9.649 -14.442,9.303 -14.594,8.934 -14.698,8.548 -14.75,8.152 -14.75,7.952 -14.75,2.236
Bottom Solder:
  region: -14.75,-24 14.75,-24 14.75,-33.452 14.75,-33.652 14.698,-34.048 14.594,-34.434 14.442,-34.803 14.242,-35.149 13.999,-35.466 13.716,-35.749 13.399,-35.992 13.053,-36.192 12.684,-36.344 12.298,-36.448 11.902,-36.5 11.702,-36.5 -11.702,-36.5 -11.902,-36.5 -12.298,-36.448 -12.684,-36.344 -13.053,-36.192 -13.399,-35.992 -13.716,-35.749 -13.999,-35.466 -14.242,-35.149 -14.442,-34.803 -14.594,-34.434 -14.698,-34.048 -14.75,-33.652 -14.75,-33.452 -14.75,-25
  region: -14.75,24 14.768,24 14.768,33.452 14.768,33.652 14.716,34.048 14.612,34.434 14.459,34.803 14.259,35.149 14.016,35.466 13.734,35.749 13.417,35.992 13.071,36.192 12.702,36.344 12.316,36.448 11.919,36.5 11.72,36.5 -11.702,36.5 -11.902,36.5 -12.298,36.448 -12.684,36.344 -13.053,36.192 -13.399,35.992 -13.716,35.749 -13.999,35.466 -14.242,35.149 -14.442,34.803 -14.594,34.434 -14.698,34.048 -14.75,33.652 -14.75,33.452 -14.75,28.75
  region: -14.75,-1.5 14.75,-1.5 14.75,7.952 14.75,8.152 14.698,8.548 14.594,8.934 14.442,9.303 14.242,9.649 13.999,9.966 13.716,10.249 13.399,10.492 13.053,10.692 12.684,10.844 12.298,10.948 11.902,11 11.702,11 -11.702,11 -11.902,11 -12.298,10.948 -12.684,10.844 -13.053,10.692 -13.399,10.492 -13.716,10.249 -13.999,9.966 -14.242,9.649 -14.442,9.303 -14.594,8.934 -14.698,8.548 -14.75,8.152 -14.75,7.952 -14.75,2.236
Mechanical 1:
  lines w0.254: -24.54,-15.786 ccw(c-24.286,-15.786) -24.286,-16.04 -19.714,-16.04 ccw(c-19.714,-15.786) -19.46,-15.786 -19.46,-11.214 ccw(c-19.714,-11.214) -19.714,-10.96 -22,-10.96 -24.286,-10.96 ccw(c-24.286,-11.214) -24.54,-11.214 -24.54,-15.786 ; -24.54,11.214 ccw(c-24.286,11.214) -24.286,10.96 -22,10.96 -19.714,10.96 ccw(c-19.714,11.214) -19.46,11.214 -19.46,15.786 ccw(c-19.714,15.786) -19.714,16.04 -24.286,16.04 ccw(c-24.286,15.786) -24.54,15.786 -24.54,11.214 ; 19.46,-15.786 ccw(c19.714,-15.786) 19.714,-16.04 24.286,-16.04 ccw(c24.286,-15.786) 24.54,-15.786 24.54,-11.214 ccw(c24.286,-11.214) 24.286,-10.96 22,-10.96 19.714,-10.96 ccw(c19.714,-11.214) 19.46,-11.214 19.46,-15.786 ; 19.46,11.214 ccw(c19.714,11.214) 19.714,10.96 22,10.96 24.286,10.96 ccw(c24.286,11.214) 24.54,11.214 24.54,15.786 ccw(c24.286,15.786) 24.286,16.04 19.714,16.04 ccw(c19.714,15.786) 19.46,15.786 19.46,11.214
3D body "Wolfspeed_XM3_Power_Module.step": height 15.76, standoff -2.5, extent -26.5,-40 26.5,40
